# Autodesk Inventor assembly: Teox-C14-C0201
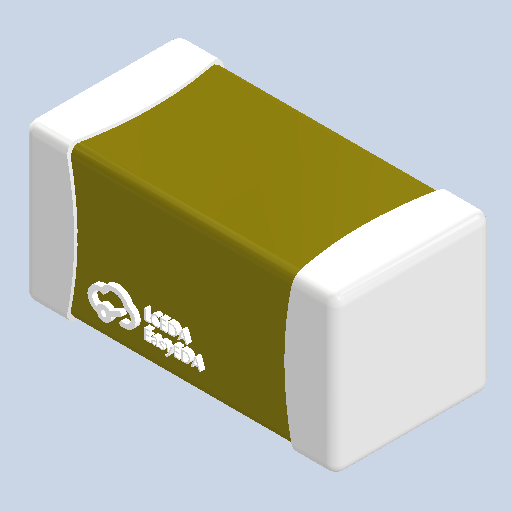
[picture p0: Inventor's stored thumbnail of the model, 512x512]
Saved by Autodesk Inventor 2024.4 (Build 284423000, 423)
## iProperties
Created: 2025-05
Part Number: Teox-C14-C0201
Document SubType Name: Assembly
Designer: AdminForWorker
Title: Teox-C14-C0201
Author: AdminForWorker
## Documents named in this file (2)
- c:\worker\convert-fusion-r02-cosv3\tmp\job-1\2\temp\files\be827049-a7f2-47ea-a815-8d9efd6bfce9\Teox-C14-C0201.iam
- c:\worker\convert-fusion-r02-cosv3\tmp\job-1\2\temp\files\be827049-a7f2-47ea-a815-8d9efd6bfce9\COMPOUND (3).ipt
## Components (1 placed, 1 different names)
1. COMPOUND (3):7
